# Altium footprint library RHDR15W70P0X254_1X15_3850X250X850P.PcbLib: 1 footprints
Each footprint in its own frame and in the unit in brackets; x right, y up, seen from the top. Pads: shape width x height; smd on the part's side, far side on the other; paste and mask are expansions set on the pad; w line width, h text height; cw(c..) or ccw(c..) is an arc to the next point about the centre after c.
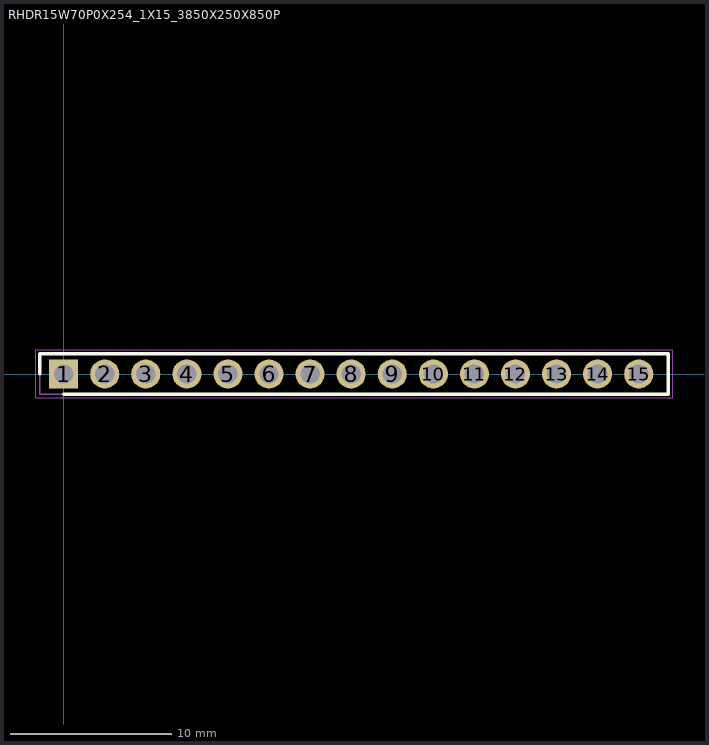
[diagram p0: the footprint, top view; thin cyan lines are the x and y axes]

## RHDR15W70P0X254_1X15_3850X250X850P [mm]
pads (15):
  rect 1.8x1.8 / inner round 1.8 / far side rect 1.8x1.8 hole 1.2: 1(0,0)
  round 1.8 hole 1.2: 2(2.54,0) 3(5.08,0) 4(7.62,0) 5(10.16,0) 6(12.7,0) 7(15.24,0) 8(17.78,0) 9(20.32,0) 10(22.86,0) 11(25.4,0) 12(27.94,0) 13(30.48,0) 14(33.02,0) 15(35.56,0)
Top Overlay:
  lines w0.2: -1.47,0 -1.47,1.25 37.38,1.25 37.38,-1.25 0,-1.25
Mechanical 15:
  lines w0.1: -1.47,-1.25 -1.47,1.25 37.38,1.25 37.38,-1.25 -1.47,-1.25
Mechanical 20:
  lines w0.05: -1.72,-1.5 -1.72,1.5 37.63,1.5 37.63,-1.5 -1.72,-1.5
